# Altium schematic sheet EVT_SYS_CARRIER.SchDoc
size 594 x 420 mm
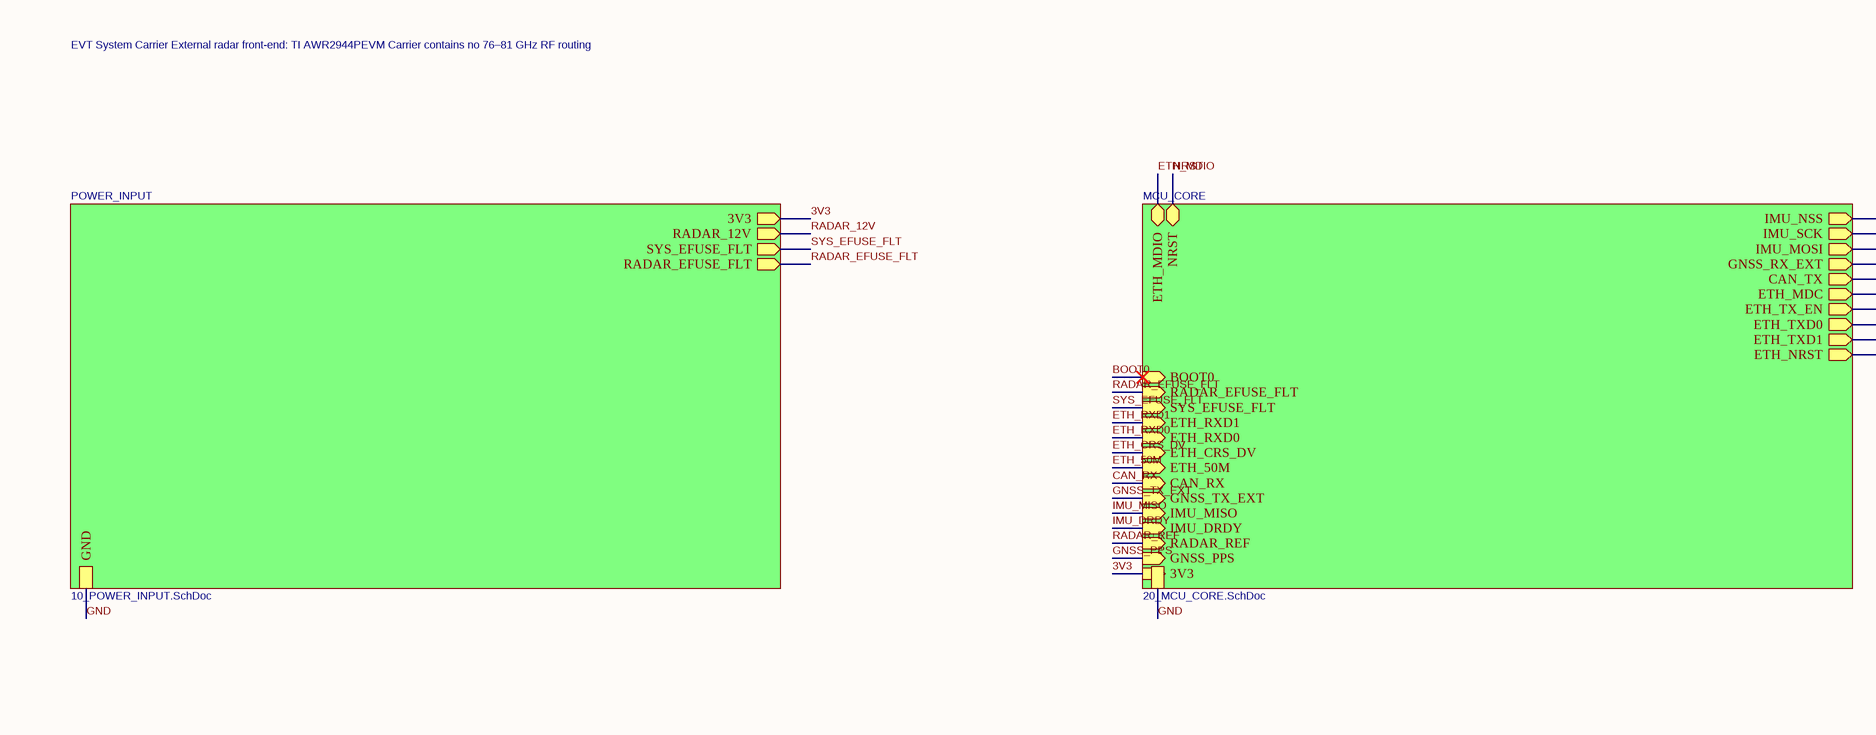
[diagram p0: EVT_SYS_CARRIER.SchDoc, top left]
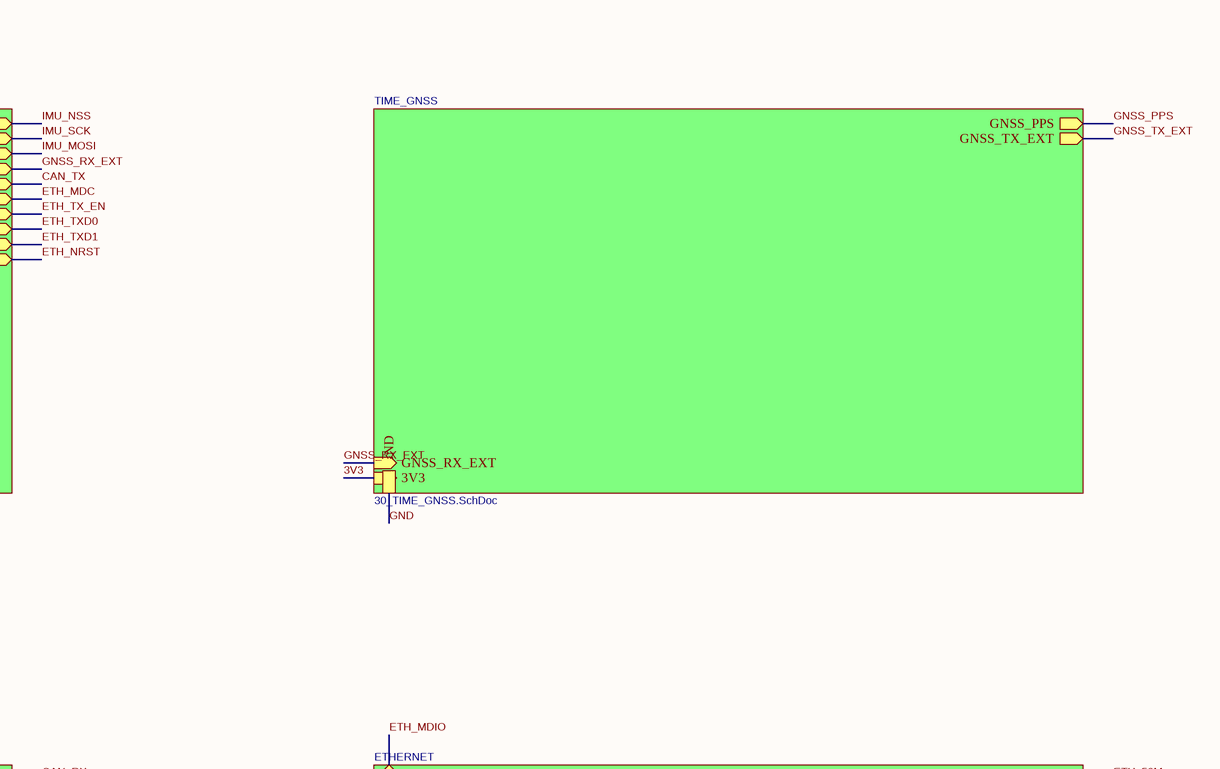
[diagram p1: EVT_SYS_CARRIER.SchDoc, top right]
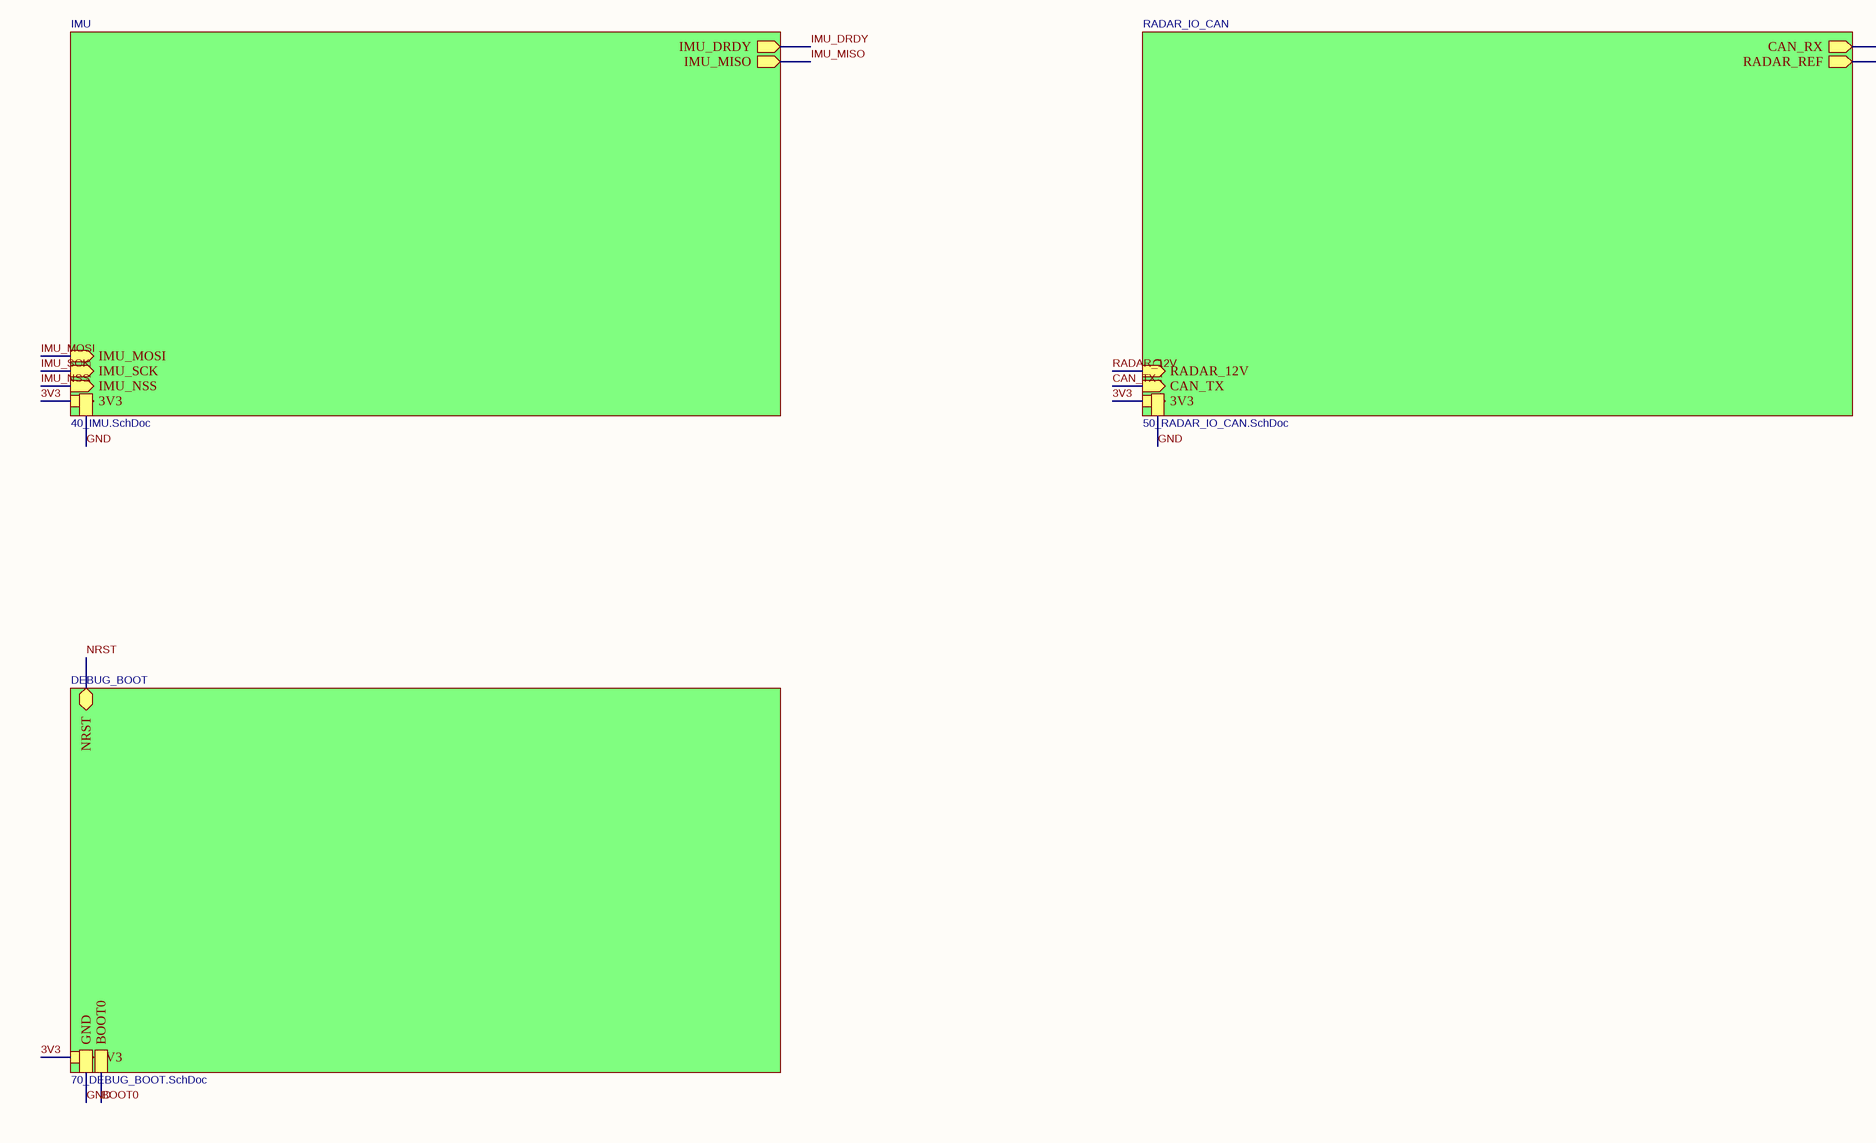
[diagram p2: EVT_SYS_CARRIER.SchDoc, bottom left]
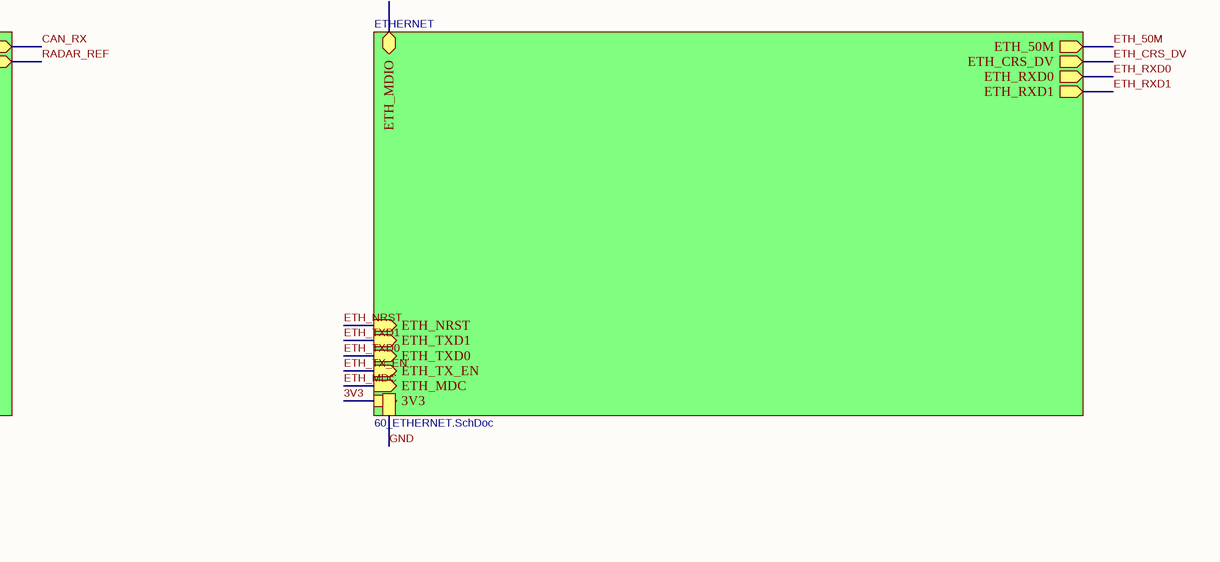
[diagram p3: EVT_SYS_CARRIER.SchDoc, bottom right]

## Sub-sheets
DEBUG_BOOT = 70_DEBUG_BOOT.SchDoc: 3V3 (in), GND, NRST (bidir), BOOT0
ETHERNET = 60_ETHERNET.SchDoc: 3V3 (in), GND, ETH_50M (out), ETH_MDIO (bidir), ETH_MDC (in), ETH_CRS_DV (out), ETH_RXD0 (out), ETH_RXD1 (out), ETH_TX_EN (in), ETH_TXD0 (in), ETH_TXD1 (in), ETH_NRST (in)
IMU = 40_IMU.SchDoc: 3V3 (in), GND, IMU_DRDY (out), IMU_NSS (in), IMU_SCK (in), IMU_MISO (out), IMU_MOSI (in)
MCU_CORE = 20_MCU_CORE.SchDoc: 3V3 (in), GND, GNSS_PPS (in), RADAR_REF (in), IMU_DRDY (in), IMU_NSS (out), IMU_SCK (out), IMU_MISO (in), IMU_MOSI (out), GNSS_RX_EXT (out), GNSS_TX_EXT (in), CAN_RX (in), CAN_TX (out), ETH_50M (in), ETH_MDIO (bidir), ETH_MDC (out), ETH_CRS_DV (in), ETH_RXD0 (in), ETH_RXD1 (in), ETH_TX_EN (out), ETH_TXD0 (out), ETH_TXD1 (out), ETH_NRST (out), SYS_EFUSE_FLT (in), RADAR_EFUSE_FLT (in), NRST (bidir), BOOT0 (in)
POWER_INPUT = 10_POWER_INPUT.SchDoc: 3V3 (out), RADAR_12V (out), SYS_EFUSE_FLT (out), RADAR_EFUSE_FLT (out), GND
RADAR_IO_CAN = 50_RADAR_IO_CAN.SchDoc: 3V3 (in), GND, CAN_TX (in), CAN_RX (out), RADAR_REF (out), RADAR_12V (in)
TIME_GNSS = 30_TIME_GNSS.SchDoc: 3V3 (in), GND, GNSS_PPS (out), GNSS_TX_EXT (out), GNSS_RX_EXT (in)

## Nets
3V3: sheet POWER_INPUT/3V3, sheet MCU_CORE/3V3, sheet TIME_GNSS/3V3, sheet IMU/3V3, sheet RADAR_IO_CAN/3V3, sheet ETHERNET/3V3, sheet DEBUG_BOOT/3V3
BOOT0: sheet MCU_CORE/BOOT0, sheet DEBUG_BOOT/BOOT0
CAN_RX: sheet MCU_CORE/CAN_RX, sheet RADAR_IO_CAN/CAN_RX
CAN_TX: sheet MCU_CORE/CAN_TX, sheet RADAR_IO_CAN/CAN_TX
ETH_50M: sheet MCU_CORE/ETH_50M, sheet ETHERNET/ETH_50M
ETH_CRS_DV: sheet MCU_CORE/ETH_CRS_DV, sheet ETHERNET/ETH_CRS_DV
ETH_MDC: sheet MCU_CORE/ETH_MDC, sheet ETHERNET/ETH_MDC
ETH_MDIO: sheet MCU_CORE/ETH_MDIO, sheet ETHERNET/ETH_MDIO
ETH_NRST: sheet MCU_CORE/ETH_NRST, sheet ETHERNET/ETH_NRST
ETH_RXD0: sheet MCU_CORE/ETH_RXD0, sheet ETHERNET/ETH_RXD0
ETH_RXD1: sheet MCU_CORE/ETH_RXD1, sheet ETHERNET/ETH_RXD1
ETH_TX_EN: sheet MCU_CORE/ETH_TX_EN, sheet ETHERNET/ETH_TX_EN
ETH_TXD0: sheet MCU_CORE/ETH_TXD0, sheet ETHERNET/ETH_TXD0
ETH_TXD1: sheet MCU_CORE/ETH_TXD1, sheet ETHERNET/ETH_TXD1
GND: sheet POWER_INPUT/GND, sheet MCU_CORE/GND, sheet TIME_GNSS/GND, sheet IMU/GND, sheet RADAR_IO_CAN/GND, sheet ETHERNET/GND, sheet DEBUG_BOOT/GND
GNSS_PPS: sheet MCU_CORE/GNSS_PPS, sheet TIME_GNSS/GNSS_PPS
GNSS_RX_EXT: sheet MCU_CORE/GNSS_RX_EXT, sheet TIME_GNSS/GNSS_RX_EXT
GNSS_TX_EXT: sheet MCU_CORE/GNSS_TX_EXT, sheet TIME_GNSS/GNSS_TX_EXT
IMU_DRDY: sheet MCU_CORE/IMU_DRDY, sheet IMU/IMU_DRDY
IMU_MISO: sheet MCU_CORE/IMU_MISO, sheet IMU/IMU_MISO
IMU_MOSI: sheet MCU_CORE/IMU_MOSI, sheet IMU/IMU_MOSI
IMU_NSS: sheet MCU_CORE/IMU_NSS, sheet IMU/IMU_NSS
IMU_SCK: sheet MCU_CORE/IMU_SCK, sheet IMU/IMU_SCK
NRST: sheet MCU_CORE/NRST, sheet DEBUG_BOOT/NRST
RADAR_12V: sheet POWER_INPUT/RADAR_12V, sheet RADAR_IO_CAN/RADAR_12V
RADAR_EFUSE_FLT: sheet POWER_INPUT/RADAR_EFUSE_FLT, sheet MCU_CORE/RADAR_EFUSE_FLT
RADAR_REF: sheet MCU_CORE/RADAR_REF, sheet RADAR_IO_CAN/RADAR_REF
SYS_EFUSE_FLT: sheet POWER_INPUT/SYS_EFUSE_FLT, sheet MCU_CORE/SYS_EFUSE_FLT

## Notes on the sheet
- EVT System Carrier
  External radar front-end: TI AWR2944PEVM
  Carrier contains no 76–81 GHz RF routing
